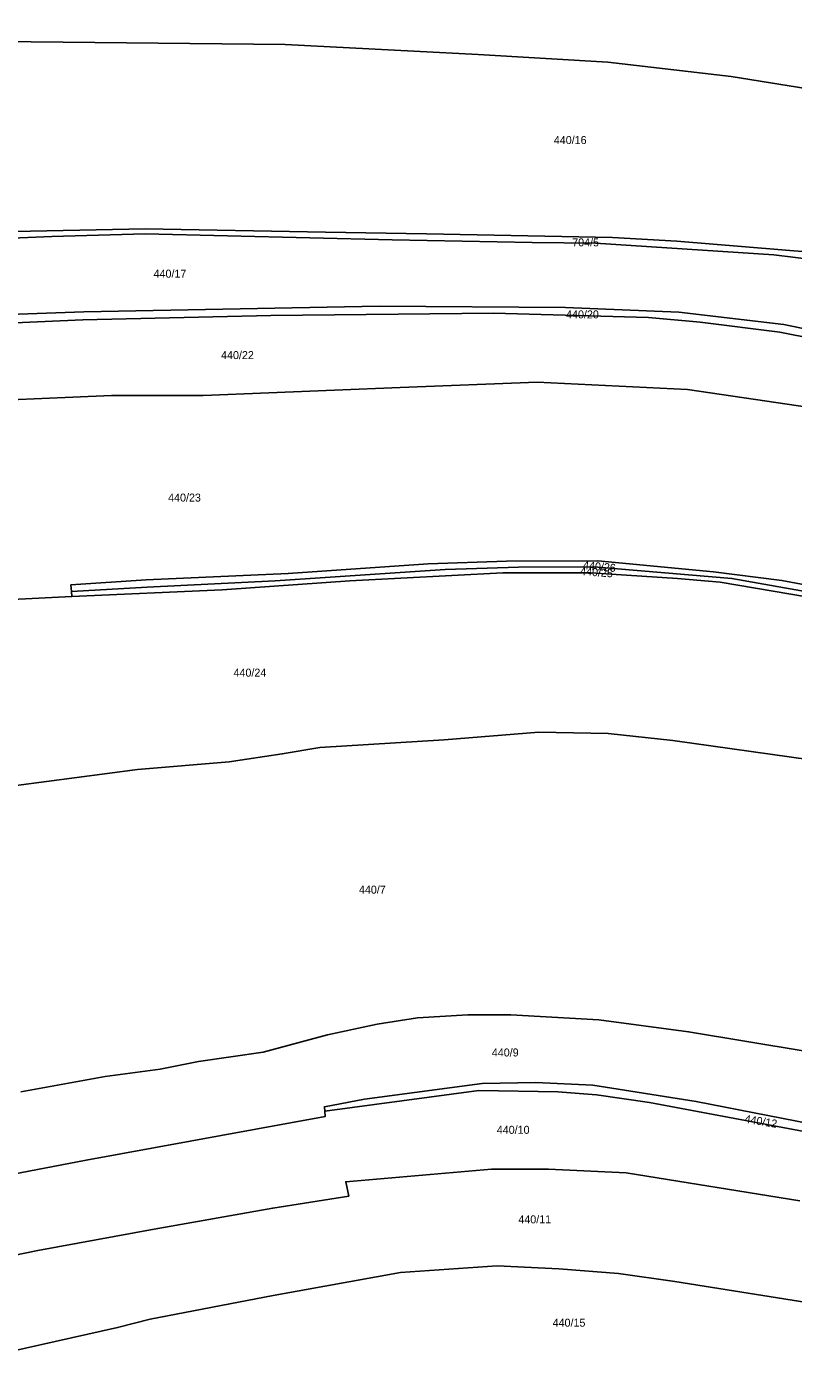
# Model space of a CAD drawing. Extents: x -629983 to -626385, y -1072828 to -1067897.
# Drawn here: x -628685.9 to -628398.5, y -1070643.4 to -1070148.2 of the extents above; entities that cross this region are included whole.
import ezdxf

# ---------------------------------------------------------------- set-up
doc = ezdxf.new("R2010")
doc.units = 0
doc.layers.add('Parcela nároku', color=7, linetype='Continuous')
doc.layers.add('Parcelní číslo', color=7, linetype='Continuous')

msp = doc.modelspace()

# ---------------------------------------------------------------- linework, layer by layer
at = {"layer": 'Parcela nároku'}
for points in [[(-628697.25, -1070109.21), (-628654.47, -1070108.86), (-628623.23, -1070110.99), (-628560.91, -1070117.14), (-628466.36, -1070130.15), (-628400.65, -1070140.75), (-628377.52, -1070144.99), (-628301.01, -1070164.65), (-628272.47, -1070172.11), (-628195.6, -1070191.34), (-628181.31, -1070194.54), (-628186.19, -1070218.59), (-628250.78, -1070202.28), (-628379.11, -1070173.77), (-628421.82, -1070167.01), (-628468.03, -1070161.59), (-628516.64, -1070158.65), (-628589.02, -1070154.96), (-628707.96, -1070153.76)], [(-628706.32, -1070228.2), (-628676.43, -1070226.93), (-628641.43, -1070225.97), (-628548.86, -1070228.15), (-628496.37, -1070229.17), (-628472.75, -1070229.44), (-628405.88, -1070233.81), (-628389.6, -1070235.8), (-628356.96, -1070242.24), (-628265.56, -1070264.98), (-628228.53, -1070273.87), (-628198.66, -1070279.99), (-628203.49, -1070303.75), (-628271.49, -1070288.24), (-628340.63, -1070272.61), (-628402.14, -1070259.92), (-628441.52, -1070255.31), (-628483.88, -1070253.57), (-628553.7, -1070253.06), (-628664.36, -1070255.18), (-628699.47, -1070256.47)], [(-628718.01, -1070289.28), (-628654.01, -1070286.5), (-628619.64, -1070286.58), (-628545.91, -1070283.54), (-628494.55, -1070281.54), (-628438.22, -1070284.3), (-628379.6, -1070292.88), (-628330.41, -1070302.87), (-628248.65, -1070322.77), (-628208.94, -1070330.57), (-628203.99, -1070306.2), (-628214, -1070304.38), (-628317.59, -1070280.52), (-628365.18, -1070270.35), (-628403.66, -1070262.78), (-628433.52, -1070259), (-628452.82, -1070257.33), (-628510.86, -1070255.71), (-628594.38, -1070256.49), (-628664.77, -1070258.22), (-628698.91, -1070259.7)], [(-628718.01, -1070289.28), (-628654.01, -1070286.5), (-628619.64, -1070286.58), (-628545.91, -1070283.54), (-628494.55, -1070281.54), (-628438.22, -1070284.3), (-628379.6, -1070292.88), (-628330.41, -1070302.87), (-628248.65, -1070322.77), (-628208.94, -1070330.57), (-628221.07, -1070390.29), (-628250.91, -1070384.06), (-628402.82, -1070355.87), (-628428.44, -1070352.58), (-628471.84, -1070348.52), (-628506.06, -1070348.62), (-628535.45, -1070349.59), (-628587.84, -1070353.27), (-628641.1, -1070355.58), (-628669.24, -1070357.52), (-628669.03, -1070360), (-628668.96, -1070361.81), (-628716.27, -1070364.26)], [(-628716.27, -1070364.26), (-628668.96, -1070361.81), (-628612.59, -1070359.43), (-628564.78, -1070355.96), (-628507.41, -1070353.04), (-628474.42, -1070352.94), (-628441.94, -1070355.07), (-628426.01, -1070356.51), (-628373.76, -1070365.31)], [(-628392.12, -1070423.1), (-628443.67, -1070415.82), (-628468.01, -1070413.18), (-628493.92, -1070412.67), (-628529.38, -1070415.59), (-628575.96, -1070418.41), (-628590.09, -1070420.85), (-628609.93, -1070423.82), (-628644.27, -1070426.67), (-628758.04, -1070441.74)], [(-628392.12, -1070423.1), (-628443.67, -1070415.82), (-628468.01, -1070413.18), (-628493.92, -1070412.67), (-628529.38, -1070415.59), (-628575.96, -1070418.41), (-628590.09, -1070420.85), (-628609.93, -1070423.82), (-628644.27, -1070426.67), (-628758.04, -1070441.74)], [(-628688.02, -1070547.57), (-628656.37, -1070541.84), (-628635.84, -1070539.06), (-628621.47, -1070536.23), (-628597.18, -1070532.71), (-628573.12, -1070526.19), (-628554.48, -1070522.13), (-628539.42, -1070519.8), (-628520.55, -1070518.72), (-628504.42, -1070518.72), (-628471.39, -1070520.57), (-628437.81, -1070524.99), (-628394.14, -1070532.32)], [(-628688.02, -1070547.57), (-628656.37, -1070541.84), (-628635.84, -1070539.06), (-628621.47, -1070536.23), (-628597.18, -1070532.71), (-628573.12, -1070526.19), (-628554.48, -1070522.13), (-628539.42, -1070519.8), (-628520.55, -1070518.72), (-628504.42, -1070518.72), (-628471.39, -1070520.57), (-628437.81, -1070524.99), (-628394.14, -1070532.32)], [(-628381.21, -1070561.65), (-628434.99, -1070551.16), (-628473.67, -1070545), (-628495.07, -1070544.02), (-628515.21, -1070544.37), (-628559.2, -1070550.25), (-628574.27, -1070553.16), (-628574.16, -1070554.81), (-628574.02, -1070556.8), (-628663.6, -1070573.19), (-628730.79, -1070586)], [(-628730.79, -1070586), (-628663.6, -1070573.19), (-628574.02, -1070556.8), (-628574.16, -1070554.81), (-628516.41, -1070547.02), (-628486.84, -1070547.54), (-628472.28, -1070548.61), (-628452.48, -1070551.49), (-628390.46, -1070563.16)], [(-628396.16, -1070588.43), (-628461.18, -1070577.86), (-628490.27, -1070576.48), (-628511.72, -1070576.56), (-628566.25, -1070581.22), (-628565.15, -1070586.63), (-628593.6, -1070591.11), (-628638, -1070598.96), (-628681.65, -1070607.07), (-628767.59, -1070624.69)], [(-628767.59, -1070624.69), (-628681.65, -1070607.07), (-628638, -1070598.96), (-628593.6, -1070591.11), (-628565.15, -1070586.63), (-628566.25, -1070581.22), (-628511.72, -1070576.56), (-628490.27, -1070576.48), (-628461.18, -1070577.86), (-628396.16, -1070588.43)], [(-628393.47, -1070626.54), (-628442.96, -1070618.68), (-628464.05, -1070615.64), (-628486.47, -1070613.85), (-628509.5, -1070612.76), (-628545.74, -1070615.25), (-628593.51, -1070623.9), (-628639.5, -1070632.73), (-628651.77, -1070635.89), (-628709.71, -1070648.87)], [(-628272.51, -1070647.92), (-628302.84, -1070643.17), (-628342.94, -1070636.07), (-628393.47, -1070626.54), (-628442.96, -1070618.68), (-628464.05, -1070615.64), (-628486.47, -1070613.85), (-628509.5, -1070612.76), (-628545.74, -1070615.25), (-628593.51, -1070623.9), (-628639.5, -1070632.73), (-628651.77, -1070635.89), (-628709.71, -1070648.87)]]:
    msp.add_lwpolyline(points, dxfattribs=at)
for points in [[(-628379.11, -1070173.77), (-628250.78, -1070202.28), (-628259.79, -1070238.1), (-628264.77, -1070261.35), (-628359.24, -1070238.39), (-628390.8, -1070232.96), (-628442.26, -1070228.67), (-628466.38, -1070227.31), (-628536.07, -1070225.95), (-628573.86, -1070225.34), (-628641.41, -1070224.05), (-628696.79, -1070225.17), (-628706.68, -1070225.65), (-628706.32, -1070228.2), (-628709.82, -1070228.71), (-628714.51, -1070190.29), (-628718.85, -1070154.67), (-628707.96, -1070153.76), (-628589.02, -1070154.96), (-628516.64, -1070158.65), (-628468.03, -1070161.59), (-628421.82, -1070167.01)], [(-628573.86, -1070225.34), (-628641.41, -1070224.05), (-628696.79, -1070225.17), (-628706.68, -1070225.65), (-628706.32, -1070228.2), (-628676.43, -1070226.93), (-628641.43, -1070225.97), (-628548.86, -1070228.15), (-628496.37, -1070229.17), (-628472.75, -1070229.44), (-628405.88, -1070233.81), (-628389.6, -1070235.8), (-628356.96, -1070242.24), (-628265.56, -1070264.98), (-628264.77, -1070261.35), (-628359.24, -1070238.39), (-628390.8, -1070232.96), (-628442.26, -1070228.67), (-628466.38, -1070227.31), (-628536.07, -1070225.95)], [(-628340.63, -1070272.61), (-628271.49, -1070288.24), (-628203.49, -1070303.75), (-628203.99, -1070306.2), (-628214, -1070304.38), (-628317.59, -1070280.52), (-628365.18, -1070270.35), (-628403.66, -1070262.78), (-628433.52, -1070259), (-628452.82, -1070257.33), (-628510.86, -1070255.71), (-628594.38, -1070256.49), (-628664.77, -1070258.22), (-628698.91, -1070259.7), (-628699.47, -1070256.47), (-628664.36, -1070255.18), (-628553.7, -1070253.06), (-628483.88, -1070253.57), (-628441.52, -1070255.31), (-628402.14, -1070259.92)], [(-628428.44, -1070352.58), (-628402.82, -1070355.87), (-628250.91, -1070384.06), (-628221.07, -1070390.29), (-628221.49, -1070392.37), (-628287.16, -1070380.06), (-628365.88, -1070365.05), (-628421.56, -1070355.07), (-628473.35, -1070350.78), (-628501.58, -1070350.88), (-628529.06, -1070351.77), (-628592.68, -1070355.96), (-628640.63, -1070358.32), (-628669.03, -1070360), (-628669.24, -1070357.52), (-628641.1, -1070355.58), (-628587.84, -1070353.27), (-628535.45, -1070349.59), (-628506.06, -1070348.62), (-628471.84, -1070348.52)], [(-628640.63, -1070358.32), (-628592.68, -1070355.96), (-628529.06, -1070351.77), (-628501.58, -1070350.88), (-628473.35, -1070350.78), (-628421.56, -1070355.07), (-628365.88, -1070365.05), (-628287.16, -1070380.06), (-628221.49, -1070392.37), (-628221.94, -1070394.59), (-628271.33, -1070385.43), (-628335.77, -1070373.02), (-628373.76, -1070365.31), (-628426.01, -1070356.51), (-628441.94, -1070355.07), (-628474.42, -1070352.94), (-628507.41, -1070353.04), (-628564.78, -1070355.96), (-628612.59, -1070359.43), (-628668.96, -1070361.81), (-628669.03, -1070360)], [(-628559.2, -1070550.25), (-628515.21, -1070544.37), (-628495.07, -1070544.02), (-628473.67, -1070545), (-628434.99, -1070551.16), (-628381.21, -1070561.65), (-628365.16, -1070564.13), (-628312.58, -1070573.99), (-628260.2, -1070583.25), (-628260.85, -1070586.44), (-628267.4, -1070585.55), (-628346.52, -1070570.66), (-628390.46, -1070563.16), (-628452.48, -1070551.49), (-628472.28, -1070548.61), (-628486.84, -1070547.54), (-628516.41, -1070547.02), (-628574.16, -1070554.81), (-628574.27, -1070553.16)]]:
    msp.add_lwpolyline(points, close=True, dxfattribs=at)

# ---------------------------------------------------------------- texts
at = {"layer": 'Parcelní číslo'}
for s, p in [('440/16', (-628488.31, -1070192.27)), ('704/5', (-628481.42, -1070230.63)), ('440/17', (-628638.28, -1070242.36)), ('440/20', (-628483.71, -1070257.62)), ('440/22', (-628612.98, -1070272.88)), ('440/23', (-628632.83, -1070326.29)), ('440/24', (-628608.32, -1070391.91)), ('440/7', (-628561.33, -1070473.25)), ('440/9', (-628511.53, -1070534.28)), ('440/10', (-628509.67, -1070563.27)), ('440/11', (-628501.6, -1070596.84)), ('440/15', (-628488.75, -1070635.58))]:
    msp.add_text(s, height=3, dxfattribs=at).set_placement(p)
for s, rotation, p in [('440/26', 354.6732, (-628477.48, -1070351.56)), ('440/25', 355.7334, (-628478.54, -1070353.82)), ('440/12', 350.5852, (-628417, -1070559.06))]:
    msp.add_text(s, height=3, rotation=rotation, dxfattribs=at).set_placement(p)

doc.saveas('drawing.dxf')
